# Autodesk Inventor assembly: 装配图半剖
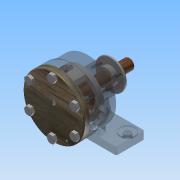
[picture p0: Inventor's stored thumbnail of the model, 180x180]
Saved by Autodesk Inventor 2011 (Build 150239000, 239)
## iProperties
Created: 2014-03
Part Number: 装配图半剖
Document SubType Name: Assembly
Designer: Administrator
Author: Administrator
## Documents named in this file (14)
- C:\Documents and Settings\Administrator\桌面\机械制图\三元子泵\装配图半剖.iam
- C:\Documents and Settings\Administrator\桌面\机械制图\三元子泵\泵体.ipt
- C:\Documents and Settings\Administrator\桌面\机械制图\三元子泵\泵盖.ipt
- C:\Documents and Settings\Administrator\桌面\机械制图\三元子泵\衬套.ipt
- C:\Documents and Settings\Administrator\桌面\机械制图\三元子泵\大滑块.ipt
- C:\Documents and Settings\Administrator\桌面\机械制图\三元子泵\垫片.ipt
- C:\Documents and Settings\Administrator\桌面\机械制图\三元子泵\螺钉M4×8.ipt
- C:\Documents and Settings\Administrator\桌面\机械制图\三元子泵\螺钉M6×16.ipt
- C:\Documents and Settings\Administrator\桌面\机械制图\三元子泵\密封环.ipt
- C:\Documents and Settings\Administrator\桌面\机械制图\三元子泵\销钉3m6×14.ipt
- C:\Documents and Settings\Administrator\桌面\机械制图\三元子泵\小滑块.ipt
- C:\Documents and Settings\Administrator\桌面\机械制图\三元子泵\小轴.ipt
- C:\Documents and Settings\Administrator\桌面\机械制图\三元子泵\压盖.ipt
- C:\Documents and Settings\Administrator\桌面\机械制图\三元子泵\转子轴.ipt
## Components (20 placed, 13 different names)
1. 泵体:1 — 插入:1, 配合:1, 配合:2, 配合:14, 配合:15, 表面齐平:1, 配合:25, 配合:26, 配合:27, 配合:30
2. 泵盖:1 — 配合:28, 配合:29, 配合:30, 配合:31, 表面齐平:2, 配合:32, 配合:33, 配合:34, 配合:35, 配合:36, 配合:37, 配合:38, 配合:39, 配合:40, 配合:41, 配合:42, 配合:43
3. 衬套:1 — 配合:2, 配合:6, 配合:7, 配合:10
4. 大滑块:1 — 配合:3, 配合:4, 配合:5, 配合:8, 配合:9, 配合:10, 配合:12
5. 垫片:1 — 配合:25, 配合:26, 配合:27, 配合:28, 配合:29
6. 螺钉M4×8:1 — 配合:17, 配合:18, 配合:19, 配合:20
7. 螺钉M6×16:1 — 配合:32, 配合:34
8. 密封环:1 — 表面齐平:1
9. 销钉3m6×14:1 — 配合:31, 表面齐平:2
10. 小滑块:1 — 配合:8, 配合:9, 配合:11, 配合:13
11. 小轴:1 — 配合:12, 配合:13
12. 压盖:1 — 配合:14, 配合:15, 配合:16, 配合:17, 配合:18, 配合:19, 配合:20, 配合:21, 配合:22, 配合:23, 配合:24
13. 转子轴:1 — 插入:1, 配合:1, 配合:3, 配合:4, 配合:5, 配合:6, 配合:7, 配合:11, 配合:16
14. 螺钉M4×8:2 — 配合:23, 配合:24
15. 螺钉M4×8:3 — 配合:21, 配合:22
16. 螺钉M6×16:2 — 配合:37, 配合:42
17. 螺钉M6×16:3 — 配合:33, 配合:35
18. 螺钉M6×16:4 — 配合:39, 配合:41
19. 螺钉M6×16:5 — 配合:36, 配合:43
20. 螺钉M6×16:6 — 配合:38, 配合:40
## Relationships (46: Mate 43, Flush 2, Insert 1)
- 插入:1 [Insert]: 泵体:1 ↔ 转子轴:1
- 配合:1 [Mate]: 泵体:1 ↔ 转子轴:1
- 配合:2 [Mate]: 泵体:1 ↔ 衬套:1
- 配合:3 [Mate]: 大滑块:1 ↔ 转子轴:1
- 配合:4 [Mate]: 大滑块:1 ↔ 转子轴:1
- 配合:5 [Mate]: 大滑块:1 ↔ 转子轴:1
- 配合:6 [Mate]: 衬套:1 ↔ 转子轴:1
- 配合:7 [Mate]: 衬套:1 ↔ 转子轴:1
- 配合:8 [Mate]: 大滑块:1 ↔ 小滑块:1
- 配合:9 [Mate]: 大滑块:1 ↔ 小滑块:1
- 配合:10 [Mate]: 衬套:1 ↔ 大滑块:1
- 配合:11 [Mate]: 小滑块:1 ↔ 转子轴:1
- 配合:12 [Mate]: 大滑块:1 ↔ 小轴:1
- 配合:13 [Mate]: 小滑块:1 ↔ 小轴:1
- 配合:14 [Mate]: 泵体:1 ↔ 压盖:1
- 配合:15 [Mate]: 泵体:1 ↔ 压盖:1
- 配合:16 [Mate]: 压盖:1 ↔ 转子轴:1
- 表面齐平:1 [Flush]: 泵体:1 ↔ 密封环:1
- 配合:17 [Mate]: 螺钉M4×8:1 ↔ 压盖:1
- 配合:18 [Mate]: 螺钉M4×8:1 ↔ 压盖:1
- 配合:19 [Mate]: 螺钉M4×8:1 ↔ 压盖:1
- 配合:20 [Mate]: 螺钉M4×8:1 ↔ 压盖:1
- 配合:21 [Mate]: 压盖:1 ↔ 螺钉M4×8:3
- 配合:22 [Mate]: 压盖:1 ↔ 螺钉M4×8:3
- 配合:23 [Mate]: 压盖:1 ↔ 螺钉M4×8:2
- 配合:24 [Mate]: 压盖:1 ↔ 螺钉M4×8:2
- 配合:25 [Mate]: 泵体:1 ↔ 垫片:1
- 配合:26 [Mate]: 泵体:1 ↔ 垫片:1
- 配合:27 [Mate]: 泵体:1 ↔ 垫片:1
- 配合:28 [Mate]: 泵盖:1 ↔ 垫片:1
- 配合:29 [Mate]: 泵盖:1 ↔ 垫片:1
- 配合:30 [Mate]: 泵体:1 ↔ 泵盖:1
- 配合:31 [Mate]: 泵盖:1 ↔ 销钉3m6×14:1
- 表面齐平:2 [Flush]: 泵盖:1 ↔ 销钉3m6×14:1
- 配合:32 [Mate]: 泵盖:1 ↔ 螺钉M6×16:1
- 配合:33 [Mate]: 泵盖:1 ↔ 螺钉M6×16:3
- 配合:34 [Mate]: 泵盖:1 ↔ 螺钉M6×16:1
- 配合:35 [Mate]: 泵盖:1 ↔ 螺钉M6×16:3
- 配合:36 [Mate]: 泵盖:1 ↔ 螺钉M6×16:5
- 配合:37 [Mate]: 泵盖:1 ↔ 螺钉M6×16:2
- 配合:38 [Mate]: 泵盖:1 ↔ 螺钉M6×16:6
- 配合:39 [Mate]: 泵盖:1 ↔ 螺钉M6×16:4
- 配合:40 [Mate]: 泵盖:1 ↔ 螺钉M6×16:6
- 配合:41 [Mate]: 泵盖:1 ↔ 螺钉M6×16:4
- 配合:42 [Mate]: 泵盖:1 ↔ 螺钉M6×16:2
- 配合:43 [Mate]: 泵盖:1 ↔ 螺钉M6×16:5
